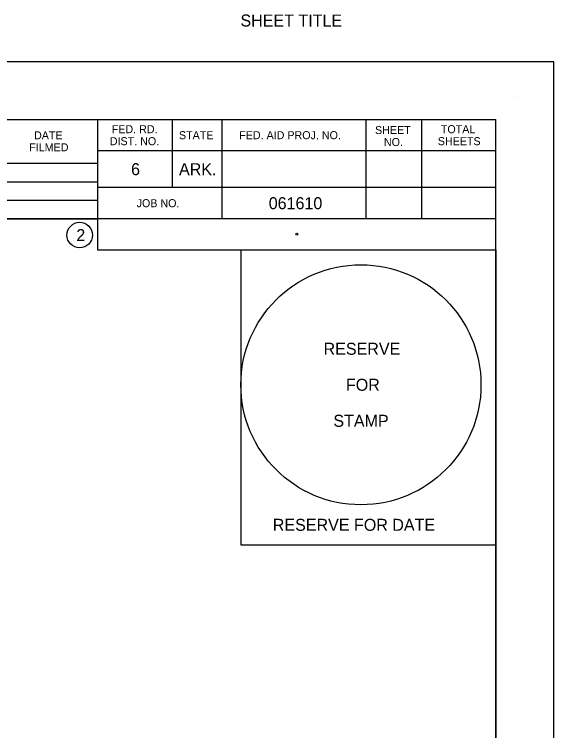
# Model space of a CAD drawing. Extents: x 759422 to 1467391, y 1662254 to 1691810.
# Drawn here: x 1466918.7 to 1467188.3, y 1691451.9 to 1691810 of the extents above; entities that cross this region are included whole.
import ezdxf

# ---------------------------------------------------------------- set-up
doc = ezdxf.new("R2010")
doc.units = 0
for name, color, linetype in [('G-ANNO-TEXT', 7, 'Continuous'), ('G-Border-Paper', 7, 'Continuous'), ('G-Border-Sheet', 7, 'Continuous'), ('G-No Plot-Anchor', 7, 'Continuous'), ('G-No Plot-Border-1', 7, 'Continuous'), ('G-No Plot-Stamp-1', 7, 'Continuous'), ('G-Table-Major', 7, 'Continuous'), ('G-Table-Minor', 7, 'Continuous')]:
    doc.layers.add(name, color=color, linetype=linetype)

msp = doc.modelspace()

# ---------------------------------------------------------------- linework, layer by layer
at = {"layer": 'G-ANNO-TEXT'}
msp.add_line((1467170.36, 1691768.89), (1467170.36, 1691768.89), dxfattribs=at)
at = {"layer": 'G-Border-Paper'}
msp.add_lwpolyline([(1467188.26, 1691786.2), (1465488.26, 1691786.2), (1465488.26, 1690686.2), (1467188.26, 1690686.2)], close=True, dxfattribs=at)
at = {"layer": 'G-Border-Sheet'}
for p in [(1465564.06, 1691757.36), (1467159.42, 1690715.04)]:
    msp.add_line(p, (1467159.42, 1691757.36), dxfattribs=at)
at = {"layer": 'G-No Plot-Anchor'}
msp.add_circle((1467059.87, 1691700.07), 0.5, dxfattribs=at)
at = {"layer": 'G-No Plot-Border-1'}
msp.add_lwpolyline([(1465564.06, 1691229.74), (1465564.06, 1691757.36), (1466762.07, 1691757.36), (1466762.07, 1691707.82), (1466960.32, 1691707.82), (1466960.32, 1691692.32), (1467031.92, 1691692.32), (1467031.92, 1691544.82), (1467159.42, 1691544.82), (1467159.42, 1691229.74)], close=True, dxfattribs=at)
at = {"layer": 'G-No Plot-Stamp-1'}
msp.add_circle((1467091.92, 1691624.82), 60, dxfattribs=at)
at = {"layer": 'G-Table-Major'}
for p, q in [((1466960.32, 1691757.36), (1466960.32, 1691692.32)), ((1466762.07, 1691735.67), (1466960.32, 1691735.67)), ((1467159.42, 1691707.82), (1466762.07, 1691707.82)), ((1466960.32, 1691692.32), (1467159.42, 1691692.32))]:
    msp.add_line(p, q, dxfattribs=at)
msp.add_lwpolyline([(1467008.64, 1691692.32), (1467159.42, 1691692.32), (1467159.42, 1691518.14)], dxfattribs=at)
msp.add_circle((1466951.38, 1691699.67), 6.38, dxfattribs=at)
at = {"layer": 'G-Table-Minor'}
for p, q in [((1466997.52, 1691757.36), (1466997.52, 1691723.37)), ((1467022.37, 1691757.36), (1467022.37, 1691707.96)), ((1467094.42, 1691757.36), (1467094.42, 1691707.96)), ((1467122.22, 1691757.36), (1467122.22, 1691707.96)), ((1467159.42, 1691741.82), (1466960.32, 1691741.82)), ((1467159.42, 1691742.76), (1467159.42, 1691742.76)), ((1466762.07, 1691726.32), (1466960.32, 1691726.32)), ((1467159.42, 1691723.37), (1466960.32, 1691723.37)), ((1466762.07, 1691717.17), (1466960.32, 1691717.17))]:
    msp.add_line(p, q, dxfattribs=at)

# ---------------------------------------------------------------- texts
at = {"layer": 'G-ANNO-TEXT'}
for s, height, p in [('SHEET TITLE', 6, (1467031.71, 1691803.91)), ('DATE', 4, (1466928.55, 1691747.51)), ('FED. RD.', 4, (1466967.39, 1691750.59)), ('STATE', 4, (1467000.97, 1691747.59)), ('FED. AID PROJ. NO.', 4, (1467031.09, 1691747.59)), ('SHEET', 4, (1467098.98, 1691750.17)), ('TOTAL', 4, (1467131.87, 1691750.59)), ('DIST. NO.', 4, (1466966.42, 1691744.59)), ('NO.', 4, (1467103.41, 1691744.17)), ('SHEETS', 4, (1467130.36, 1691744.59)), ('FILMED', 4, (1466926.14, 1691741.51)), ('6', 6, (1466977.05, 1691729.59)), ('ARK.', 6, (1467001.01, 1691729.59)), ('JOB NO.', 4, (1466979.82, 1691713.59)), ('061610', 6, (1467045.85, 1691712.59)), ('2', 6, (1466949.68, 1691696.67))]:
    msp.add_text(s, height=height, dxfattribs=at).set_placement(p)
at = {"layer": 'G-No Plot-Stamp-1'}
for s, p in [('RESERVE', (1467073.26, 1691639.82)), ('FOR ', (1467084.43, 1691621.82)), ('STAMP', (1467078.15, 1691603.82)), ('RESERVE FOR DATE', (1467047.89, 1691551.82))]:
    msp.add_text(s, height=6, dxfattribs=at).set_placement(p)

doc.saveas('drawing.dxf')
